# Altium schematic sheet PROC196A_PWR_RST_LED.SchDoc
size 431 x 279 mm; Date: Not shown in title block; ApprovedBy: Not shown in title block; CheckedBy: Not shown in title block; Author: Not shown in title block; CompanyName: Not shown in title block; Engineer: Not shown in title block; Organization: Not shown in title block; Address1: Not shown in title block; Address2: Not shown in title block; Address3: Not shown in title block; Address4: Not shown in title block; DocumentNumber: 9; Revision: Use project parameter SCH_Rev; SheetNumber: 9; SheetTotal: 25; PageSetup: Record=PageOptions¦CenterHorizontal=True¦CenterVertical=True¦PrintScale=1.00¦XCorrection=1.00¦YCorrection=1.00¦PrintKind=0¦BorderSize=5000000¦LeftOffset=0¦BottomOffset=0¦Orientation=2¦PaperLength=1000¦PaperWidth=1000¦Scale=100¦PaperSource=15¦PrintQuality=600¦MediaType=1¦DitherType=10¦PaperKind=Letter¦PrintScaleMode=1
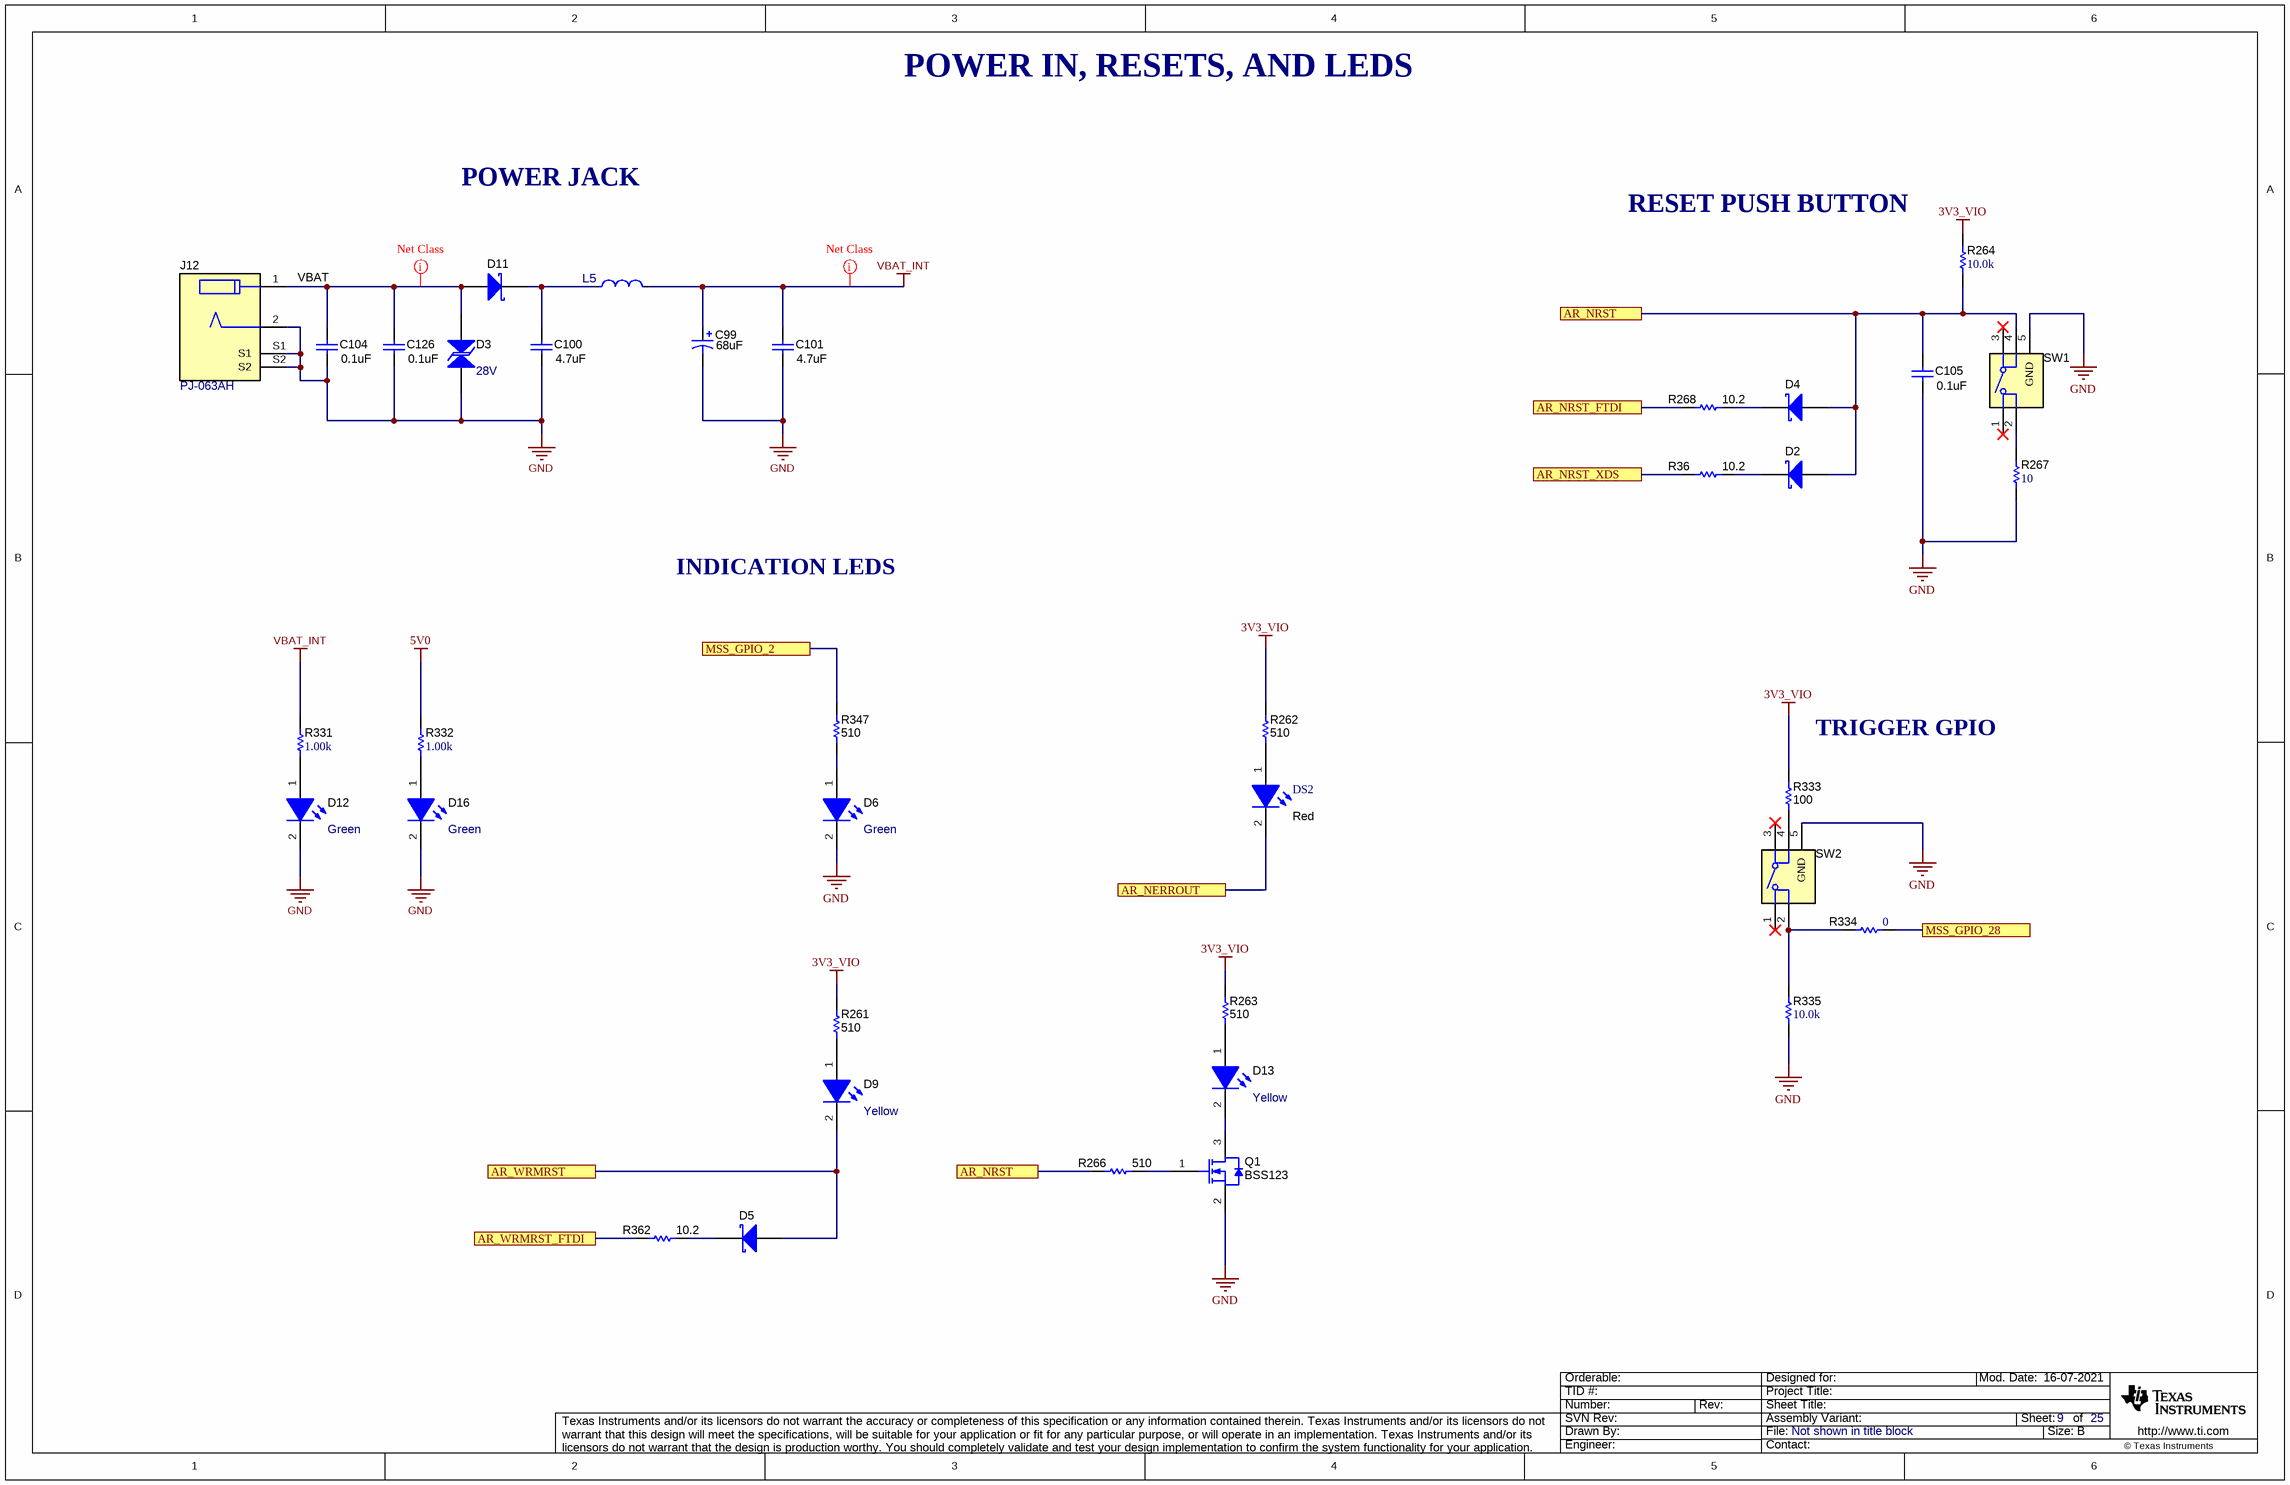
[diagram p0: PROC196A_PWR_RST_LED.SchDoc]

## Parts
C99  ValueDisplayed: 68uF  [SM_RADIAL_6.3BMM]  (hidden comment: EEHZC1V680XP)
C100  ValueDisplayed: 4.7uF  [1206_180L]  (hidden comment: C3216X7R1H475K160AC)
C101  ValueDisplayed: 4.7uF  [1206_180L]  (hidden comment: C3216X7R1H475K160AC)
C104  ValueDisplayed: 0.1uF  [0603L]  (hidden comment: CGA3E3X8R1H104K080AB)
C105  ValueDisplayed: 0.1uF  [0402L]  (hidden comment: GCM155R71C104KA55D)
C126  ValueDisplayed: 0.1uF  [0603L]  (hidden comment: CGA3E3X8R1H104K080AB)
D2  SMS3923-040LF  [SOD-882]  (value not drawn)
D3  value 28V  [SOD-123]  (hidden comment: ATV02W280B-HF)
D4  SMS3923-040LF  [SOD-882]  (value not drawn)
D5  SMS3923-040LF  [SOD-882]  (value not drawn)
D6  value Green  [SML_Green_0805]  (hidden comment: SML-LXT0805GW-TR)
D9  value Yellow  [SML-E1_Yellow]  (hidden comment: SML-E12Y8WT86)
D11  PMEG3050EP,115  [SOD-128]  (value not drawn)
D12  value Green  [SML_Green_0805]  (hidden comment: SML-LXT0805GW-TR)
D13  value Yellow  [SML-E1_Yellow]  (hidden comment: SML-E12Y8WT86)
D16  value Green  [SML_Green_0805]  (hidden comment: SML-LXT0805GW-TR)
DS2  value Red  [LS L29K_Red]  (hidden comment: LS L29K-G1J2-1-Z)
J12  PJ-063AH  [CUI_PJ-063AH]
L5  XAL4030-472MEC  [FP-XAL4030-472MEC_SMD2-MFG]  (value not drawn)
Q1  BSS123  [SOT-23]
R36  ValueDisplayed: 10.2  [0402L]  (hidden comment: CRCW040210R2FKED)
R261  ValueDisplayed: 510  [0402L]  (hidden comment: ERJ-2GEJ511X)
R262  ValueDisplayed: 510  [0402L]  (hidden comment: ERJ-2GEJ511X)
R263  ValueDisplayed: 510  [0402L]  (hidden comment: ERJ-2GEJ511X)
R264  ValueDisplayed: 10.0k  [0402L]  (hidden comment: CRCW040210K0FKED)
R266  ValueDisplayed: 510  [0402L]  (hidden comment: ERJ-2GEJ511X)
R267  ValueDisplayed: 10  [0402L]  (hidden comment: CRCW040210R0JNED)
R268  ValueDisplayed: 10.2  [0402L]  (hidden comment: CRCW040210R2FKED)
R331  ValueDisplayed: 1.00k  [0402L]  (hidden comment: CRCW04021K00FKED)
R332  ValueDisplayed: 1.00k  [0402L]  (hidden comment: CRCW04021K00FKED)
R333  ValueDisplayed: 100  [0402L]  (hidden comment: ERJ-2GEJ101X)
R334  ValueDisplayed: 0  [0201L]  (hidden comment: CRCW02010000Z0ED)
R335  ValueDisplayed: 10.0k  [0402L]  (hidden comment: CRCW040210K0FKED)
R347  ValueDisplayed: 510  [0402L]  (hidden comment: ERJ-2GEJ511X)
R362  ValueDisplayed: 10.2  [0402L]  (hidden comment: CRCW040210R2FKED)
SW1  KMR243GLFG  [SW_KMR243GLFG]  (value not drawn)
SW2  KMR243GLFG  [SW_KMR243GLFG]  (value not drawn)

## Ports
AR_NERROUT, AR_NRST, AR_NRST_FTDI, AR_NRST_XDS, AR_WRMRST, AR_WRMRST_FTDI, MSS_GPIO_2, MSS_GPIO_28

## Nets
3V3_VIO: R261.2 R262.2 R263.2 R264.2 R333.2
5V0: R332.2
GND: C99.2(-) C100.2 C101.2 C104.2 C105.1 C126.2 D3.1 D6.2(K) D12.2(K) D16.2(K) J12.2 J12.S1 J12.S2 Q1.2(S) R267.1 R335.1 SW1.5(GND) SW2.5(GND)
VBAT_INT: C99.1(+) C101.1 L5.2 R331.2
AR_NERROUT: DS2.2(K) ; port AR_NERROUT
AR_NRST: C105.2 D2.2(A) D4.2(A) R264.1 R266.1 SW1.4 ; port AR_NRST
AR_NRST_FTDI: R268.1 ; port AR_NRST_FTDI
AR_NRST_XDS: R36.1 ; port AR_NRST_XDS
AR_WRMRST: D5.2(A) D9.2(K) ; port AR_WRMRST
AR_WRMRST_FTDI: R362.1 ; port AR_WRMRST_FTDI
MSS_GPIO_2: R347.2 ; port MSS_GPIO_2
MSS_GPIO_28: R334.2 ; port MSS_GPIO_28
NetC100_1: C100.1 D11.1(K) L5.1
NetC104_1: C104.1 C126.1 D3.2 D11.2(A) J12.1
NetD2_1: D2.1(K) R36.2
NetD4_1: D4.1(K) R268.2
NetD5_1: D5.1(K) R362.2
NetD6_1: D6.1(A) R347.1
NetD9_1: D9.1(A) R261.1
NetD12_1: D12.1(A) R331.1
NetD13_1: D13.1(A) R263.1
NetD13_2: D13.2(K) Q1.3(D)
NetD16_1: D16.1(A) R332.1
NetDS2_1: DS2.1(A) R262.1
NetQ1_1: Q1.1(G) R266.2
NetR267_2: R267.2 SW1.2
NetR333_1: R333.1 SW2.4
NetR334_1: R334.1 R335.2 SW2.2

Not connected (* = marked no-connect by the designer): SW1 1* 3*; SW2 1* 3*

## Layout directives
net class PWR: NetC104_1, VBAT_INT

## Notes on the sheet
- POWER IN, RESETS, AND LEDS
- POWER JACK
- RESET PUSH BUTTON
- VBAT
- INDICATION LEDS
- (near R333) TRIGGER GPIO

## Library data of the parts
C99 = CMP-0012608-3: CAP, Polymer Hybrid, 68 uF, 35 V, +/- 20%, 35 ohm, 6.3x7.7 SMD; Manufacturer: Panasonic; TaMin_C: -55°C; ESR_ohm: 35; Polarized: Y; SizeAreaWB_mm2: 79.98; Value1: 35 ohm; Value: 68uF; TaMax_C: 125°C; SizeZ_mm: 7.7; SizeX_mm: 7.3; SizeY_mm: 6.6; Value2: 35V; SizeArea_mm2: 48.18; CompType: Capacitor; Cap_F: 68µF; IRMS_A: 1.4A; AEC Category: Q200
C100 C101 = CMP-0008702-2: CAP, CERM, 4.7 uF, 50 V, +/- 10%, X7R, 1206; Manufacturer: TDK; TaMin_C: -55°C; ESR_ohm: 3.158m; Polarized: N; SizeAreaWB_mm2: 10.92; Value1: 0.003158 ohm; U/M: EA; Value: 4.7uF; TaMax_C: 125°C; SizeZ_mm: 1.8; SizeX_mm: 3.2; SizeY_mm: 1.6; Cap_Case: 1206_180; Value2: 50V; SizeArea_mm2: 5.12; Cap_F: 4.7µF; IRMS_A: 4.08379A; AEC Category: Q200
C104 C126 = CMP-0007104-4: CAP, CERM, 0.1 uF, 50 V, +/- 10%, X8R, AEC-Q200 Grade 0, 0603; Manufacturer: TDK; TaMin_C: -55°C; Polarized: N; SizeAreaWB_mm2: 4.68; Value1: Unknown; U/M: EA; Value: 0.1uF; TaMax_C: 150°C; SizeZ_mm: 1; SizeX_mm: 1.6; SizeY_mm: 0.8; Cap_Case: 0603; Value2: 50V; SizeArea_mm2: 1.28; AEC Qualified: Y; Cap_F: 100nF; AEC Grade: 0; AEC Category: Q200
C105 = CMP-0006351-2: CAP, CERM, 0.1 uF, 16 V, +/- 10%, X7R, 0402; Manufacturer: MuRata; TaMin_C: -55°C; Polarized: N; SizeAreaWB_mm2: 3; Value1: Unknown; U/M: EA; Value: 0.1uF; TaMax_C: 125°C; SizeZ_mm: 0.6; SizeX_mm: 1; SizeY_mm: 0.5; Cap_Case: 0402; Value2: 16V; Cap_F: 100nF; AEC Category: Q200
D2 D4 D5 = CMP-0078187-3: Diode, Schottky,  V, 0.01 A, SOD-882; Manufacturer: Skyworks Solutions; SizeArea_mm2: 0.6; SizeAreaWB_mm2: 3.2; Io_A: 10mA; SizeX_mm: 1; Value1: 0.01A; SizeZ_mm: 0.5; Value2: 0.34V; AEC Category: Q101; Vf_V: 340mV; TJmax_C: 150°C; AEC Qualified: N
D3 = CMP-0005735-3: Diode, TVS, Bi, 28 V, 45.4 Vc, AEC-Q101, SOD-123; Manufacturer: Comchip Technology; SizeAreaWB_mm2: 13.095; Value1: 200W; SizeZ_mm: 1.35; SizeX_mm: 3.85; SizeY_mm: 1.7; SizeArea_mm2: 6.545; AEC Qualified: Y; AEC Category: Q101; Ipp: 4.41A; Vbr_Max: 34.4V; Vbr_Min: 31.1V; Vc: 45.4V
D6 D12 D16 = CMP-0003042-3: LED, Green, SMD; Manufacturer: Lumex; SizeZ_mm: 0.8; Power_TotalModule: 50mW; Value2: 2V; SizeY_mm: 1.25; Tjmax_C: 80°C; SizeX_mm: 2; SizeAreaWB_mm2: 6.75; Ir_A: 100µA; Angle: 140; Vr_V: 5V; Io_A: 20mA; Value1: 0.05W; SizeArea_mm2: 2.5
D9 D13 = CMP-0002977-3: LED, Yellow, SMD; Manufacturer: Rohm; Vf_V: 2.2V; Vr_V: 5V; Ir_A: 10µA; Tjmax_C: 85°C; Io_A: 20mA; LuminousIntensity_IV: 63; Power_TotalModule: 54mW; Value1: 0.054W
D11 = CMP-0077017-3: Diode, Schottky, 30 V, 5 A, SOD-128; Manufacturer: Nexperia; Vf_V: 360mV; Vr_V: 30V; Green_Lifecycle: Not Set; SizeZ_mm: 1.1; SizeY_mm: 2.5; Value2: 0.36V; Value1: 5A; SizeAreaWB_mm2: 19.6; AEC Category: Q101; SizeArea_mm2: 11.5; Green_REACh: Incomplete; TJmax_C: 150°C; SizeX_mm: 4.6; Value: 30V
DS2 = CMP-0002902-2: LED, Red, SMD; Manufacturer: OSRAM; Io_A: 20mA; Vr_V: 12V; Tjmax_C: 110°C; Value1: W; Angle: 160; Vf_V: 1.8V
J12 = CMP-0079472-1: DC POWER JACK, R/A, TH; Manufacturer: CUI Inc.; Gender: Male; Cert_UL: Y; Current_A: 8A; Voltage_V: 24V
L5 = CMP-0089502-2: Power Inductor (SMD), 4.7 µH, 5.1 A, Shielded, 4.5 A, XAL40xx Series, 4mm x 4mm x 3.1mm; Manufacturer: Coilcraft; Material: Composite; TaMin_C: -40°C; Test Frequency: 1MHz; Shrouded: true; Irms: 5.1A; AEC Grade: Grade 1; Tolerance_%: 20%; Isat: 4.5A; AEC Qualified: Yes; Standoff Height: 0.08mm; DCR_ohm: 0.0441; Self Resonant Frequency: 36MHz; Ind_H: 4.7µH; TaMax_C: +125°C; Value: 4.7µH
Q1 = CMP-0000947-2: MOSFET, N-CH, 100 V, 0.17 A, SOT-23; Alternate Manufacturer: None; Manufacturer: Fairchild Semiconductor; SizeZ_mm: 1.1; ChType: N; Value2: 1.8 nC; Value1: 1; VdsMax_V: 100V; SizeX_mm: 2.5; SizeY_mm: 3; Vgs_V: 20V; Value: 100V; Rdson45_ohm: 10; SizeArea_mm2: 7.5; AEC Category: Q101; IdsMax_A: 1.7dA; SizeAreaWB_mm2: 14; U/M: EA; QgTyp_nC: 1.8
R36 R268 R362 = CMP-0025964-3: RES, 10.2, 1%, 0.063 W, AEC-Q200 Grade 0, 0402; Manufacturer: Vishay-Dale; Power_W: 63mW; TempCo: 100 ppm/C; Value_Code: 10R2; Value: 10.2; EIA_Code: E96; SizeX_mm: 1; SizeY_mm: 0.5; SizeZ_mm: 0.6; Value2: 0.063W; AEC Qualified: Y; VDC_V: 50V; AEC Category: Q200; AEC Grade: 0
R261-R263 R266 R347 = CMP-0078212-1: RES, 510, 5%, 0.1 W, AEC-Q200 Grade 0, 0402; Manufacturer: Panasonic; Value_Code: 510R; SizeArea_mm2: 0.5; AEC Qualified: Y; AEC Category: Q200; Value: 510; SizeZ_mm: 0.6; EIA_Code: E24; TempCo: 200 ppm/C; AEC Grade: 0; Power_W: 100mW; VDC_V: 50V; Value2: 0.1W; U/M: EA; SizeX_mm: 1
R264 R335 = CMP-0025958-3: RES, 10.0 k, 1%, 0.063 W, AEC-Q200 Grade 0, 0402; Manufacturer: Vishay-Dale; Power_W: 63mW; TempCo: 100 ppm/C; Value_Code: 10k0; Value: 10.0k; EIA_Code: E96; Res_ohm: 10k; SizeX_mm: 1; SizeY_mm: 0.5; SizeZ_mm: 0.6; Value2: 0.063W; AEC Qualified: Y; VDC_V: 50V; AEC Category: Q200; AEC Grade: 0
R267 = CMP-0026827-3: RES, 10, 5%, 0.063 W, AEC-Q200 Grade 0, 0402; Manufacturer: Vishay-Dale; Power_W: 63mW; TempCo: 200 ppm/C; Value_Code: 10R0; Value: 10; EIA_Code: E24; SizeX_mm: 1; SizeY_mm: 0.5; SizeZ_mm: 0.6; Value2: 0.063W; AEC Qualified: Y; VDC_V: 50V; AEC Category: Q200; AEC Grade: 0
R331 R332 = CMP-0026071-3: RES, 1.00 k, 1%, 0.063 W, AEC-Q200 Grade 0, 0402; Manufacturer: Vishay-Dale; Power_W: 63mW; TempCo: 100 ppm/C; Value_Code: 1k00; Value: 1.00k; EIA_Code: E96; Res_ohm: 1k; SizeX_mm: 1; SizeY_mm: 0.5; SizeZ_mm: 0.6; Value2: 0.063W; AEC Qualified: Y; VDC_V: 50V; AEC Category: Q200; AEC Grade: 0
R333 = CMP-0026993-2: RES, 100, 5%, 0.1 W, AEC-Q200 Grade 0, 0402; Manufacturer: Panasonic; Power_W: 100mW; TempCo: 200 ppm/C; Value_Code: 100R; U/M: EA; Value: 100; EIA_Code: E24; SizeX_mm: 1; SizeY_mm: 0.5; SizeZ_mm: 0.6; Value2: 0.1W; AEC Qualified: Y; AEC Grade: 0; AEC Category: Q200
R334 = CMP-0027008-4: RES, 0, 5%, 0.05 W, 0201; Manufacturer: Vishay-Dale; Power_W: 50mW; TempCo: ppm/C; Value_Code: 0000; Value: 0; EIA_Code: E24; SizeX_mm: 0.6; SizeY_mm: 0.3; SizeZ_mm: 0.26; Value2: 0.05W; SizeArea_mm2: 0.18; AEC Qualified: N; AEC Category: Q200
SW1 SW2 = CMP-0002325-1: Switch, SPST-NO, Off-Mom, 0.01 A, 32 VDC, SMD; Manufacturer: C&K Components; CurrentRating_mA: 10A; PositionCount: 1; SizeX_mm: 4.6; SizeY_mm: 2.8; SizeZ_mm: 1.9; SizeArea_mm2: 12.88; VDC_V: 32V; SizeAreaWB_mm2: 21.28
